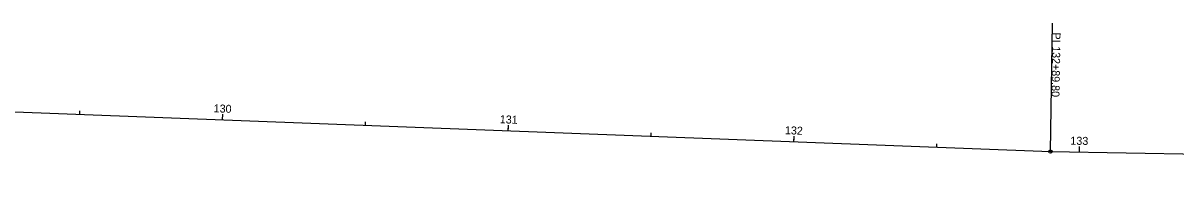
# Model space of a CAD drawing. Extents: x 2003596 to 2006888, y 572582 to 572983.
# Drawn here: x 2005664.2 to 2006067.5, y 572582.8 to 572642.2 of the extents above; entities that cross this region are included whole.
import ezdxf

# ---------------------------------------------------------------- set-up
doc = ezdxf.new("R2010")
doc.units = 0
for name, color, linetype in [('DR_X_Ditch', 7, 'Continuous'), ('PM_X_Surveyed_Line', 7, 'Continuous'), ('PV_X_COP', 7, 'Continuous'), ('RD_X_Fence', 7, 'Continuous'), ('SV_X_Top_of_Bank', 7, 'Continuous'), ('UT_X_Water_Cells', 7, 'Continuous'), ('VG_X_Tree_Line_Lt', 7, 'Continuous')]:
    doc.layers.add(name, color=color, linetype=linetype)

msp = doc.modelspace()

# ---------------------------------------------------------------- linework, layer by layer
at = {"layer": 'DR_X_Ditch'}
for p, q in [((2005684.07, 572610.28), (2005684.12, 572611.48)), ((2005734.03, 572608.36), (2005734.11, 572610.36)), ((2005784, 572606.44), (2005784.04, 572607.64)), ((2005833.96, 572604.53), (2005834.04, 572606.53)), ((2005883.92, 572602.61), (2005883.97, 572603.81)), ((2005933.89, 572600.69), (2005933.96, 572602.69)), ((2005983.85, 572598.78), (2005983.9, 572599.98)), ((2006033.82, 572597.08), (2006033.85, 572599.08))]:
    msp.add_line(p, q, dxfattribs=at)
at = {"layer": 'PM_X_Surveyed_Line'}
for p, q in [((2005031.48, 572635.32), (2006023.62, 572597.25)), ((2006023.62, 572597.25), (2006884.1, 572582.77))]:
    msp.add_line(p, q, dxfattribs=at)
at = {"layer": 'PV_X_COP'}
msp.add_line((2006023.62, 572597.25), (2006024.38, 572642.24), dxfattribs=at)
msp.add_circle((2006023.62, 572597.25), 0.6, dxfattribs=at)
at = {"layer": 'RD_X_Fence'}
for p, q in [((2005734.03, 572608.36), (2005734.11, 572610.36)), ((2005833.96, 572604.53), (2005834.01, 572605.73)), ((2005933.89, 572600.69), (2005933.93, 572601.89)), ((2006033.82, 572597.08), (2006033.84, 572598.28))]:
    msp.add_line(p, q, dxfattribs=at)
at = {"layer": 'SV_X_Top_of_Bank'}
msp.add_line((2006023.62, 572597.25), (2006024.38, 572642.24), dxfattribs=at)
msp.add_circle((2006023.62, 572597.25), 0.6, dxfattribs=at)
at = {"layer": 'UT_X_Water_Cells'}
msp.add_line((2005734.03, 572608.36), (2005734.11, 572610.36), dxfattribs=at)
at = {"layer": 'VG_X_Tree_Line_Lt'}
msp.add_line((2006023.62, 572597.25), (2006024.38, 572642.24), dxfattribs=at)
msp.add_circle((2006023.62, 572597.25), 0.6, dxfattribs=at)

# ---------------------------------------------------------------- texts
at = {"layer": 'DR_X_Ditch'}
for s, rotation, p in [('130', 357.8026, (2005730.85, 572611.03)), ('131', 357.8026, (2005830.95, 572607.19)), ('132', 357.8026, (2005930.71, 572603.36)), ('133', 359.0359, (2006030.6, 572599.68))]:
    msp.add_text(s, height=2.8, rotation=rotation, dxfattribs=at).set_placement(p)
at = {"layer": 'PV_X_COP'}
for s, p in [('PI', (2006024.37, 572638.95)), ('132+89.80', (2006024.29, 572634.17))]:
    msp.add_text(s, height=2.8, rotation=269.0359, dxfattribs=at).set_placement(p)
at = {"layer": 'RD_X_Fence'}
msp.add_text('130', height=2.8, rotation=357.8026, dxfattribs=at).set_placement((2005730.85, 572611.03))
at = {"layer": 'SV_X_Top_of_Bank'}
for s, p in [('PI', (2006024.37, 572638.95)), ('132+89.80', (2006024.29, 572634.17))]:
    msp.add_text(s, height=2.8, rotation=269.0359, dxfattribs=at).set_placement(p)
at = {"layer": 'UT_X_Water_Cells'}
msp.add_text('130', height=2.8, rotation=357.8026, dxfattribs=at).set_placement((2005730.85, 572611.03))
at = {"layer": 'VG_X_Tree_Line_Lt'}
for s, p in [('PI', (2006024.37, 572638.95)), ('132+89.80', (2006024.29, 572634.17))]:
    msp.add_text(s, height=2.8, rotation=269.0359, dxfattribs=at).set_placement(p)

doc.saveas('drawing.dxf')
